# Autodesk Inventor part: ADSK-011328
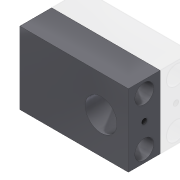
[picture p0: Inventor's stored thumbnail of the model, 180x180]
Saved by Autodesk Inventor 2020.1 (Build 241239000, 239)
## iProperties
Created: 1999-12
Part Number: ADSK-011328
Material: Acier doux
Description: PLT-04,FH,CP,10,022,032,955C,SUPPORT,SHAFT
Document SubType Name: Modeling
Designer: sspink
Density: 7.86 g/cm^3
Appearance: Metal-Steel(Polish)
Mass: 748.058 g
Surface Area: 230.906 cm^2
Volume: 95.1728 cm^3
Control State: 0
Checked Out: False
Last Check In By: sspink
Last Check In Date: 1999-12-22
Master: False
Shininess: 0.0
Length Units: 11269
Angle Units: 11279
Time Units: 11290
Mass Units: 11283
Length Display Precision: 3
Angle Display Precision: 2
Compacted: True
Dimensions: 85,5x57x25 mm
Mass: 0,748 kg
DocNumber: ADSK-011328.ipt
Folder: 01 - Themengebiete\Simplification\01 - Packaging machine\
VDS_Category: 3D Komponenten
Density: 0.0
Volumn: 0.0
Area: 0.0
PropertySet Name: Model Information
Author: sspink
Revision Number: -
Title: Support
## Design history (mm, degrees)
node "Solide1"
  node "Extrusion1" dims "d2" = 25, "d3" = 0
  node "Hole1" dims "d5" = 25, "d6" = 9.525, "d7" = 6.35, "d8" = 60 deg, "d9" = 19.05, "d10" = 118 deg, "d26" = 6
  node "Hole2" dims "d13" = 9, "d14" = 15, "d15" = 15, "d16" = 60 deg, "d17" = 19.05, "d18" = 118 deg, "d28" = 6
  node "Hole3" dims "d19" = 4.134, "d20" = 9.525, "d21" = 6.35, "d22" = 60 deg, "d23" = 14.2, "d24" = 118 deg, "d29" = 10
sketch "Sketch1"
  geometry: L1 (-42.75, 28.5)-(42.75, 28.5); L2 (42.75, 28.5)-(42.75, -28.5); L3 (42.75, -28.5)-(-42.75, -28.5); L4 (-42.75, -28.5)-(-42.75, 28.5); 3 further points
  constraints: 8 end point, 2 midpoint, 2 parallel, 1 horizontal, 1 horizontal alignment, 1 perpendicular, 1 vertical alignment
  dimensions: "d0" = 85.5 distance of L1.start L1.end; "d1" = 57 distance of L1.end L2.end
sketch "Sketch2"
  geometry: L1 (-42.75, -28.5)-(-42.75, 28.5) reference; L2 (42.75, 28.5)-(42.75, -28.5) reference; L3 (-42.75, 0)-(42.75, 0); 1 further point
  constraints: 2 end point, 2 midpoint, 1 point on line
  dimensions: "d4" = 21.5 distance from line of point (21.25, 0) L2
sketch "Sketch3"
  geometry: L1 (-12.5, 47.5)-(-12.5, 9.5); L2 (0, 57)-(-25, 57) reference; L3 (-25, 57)-(-25, 0) reference; 3 further points
  constraints: 3 midpoint, 2 end point, 1 horizontal alignment, 1 vertical, 1 vertical alignment
  dimensions: "d27" = 38 distance of L1.start L1.end
workplane "Work Plane1"
node "Corps solides"
node "Corps surfaciques"
sketch "Sketch4"
  geometry: L1 (-25, 57)-(-25, 0) reference; L2 (0, 0)-(-25, 0) reference; L3 (0, 0)-(0, 57) reference; L4 (0, 57)-(-25, 57) reference; L5 (-12.5, 57)-(-12.5, 0); L6 (-25, 28.5)-(0, 28.5); 1 further point
  constraints: 5 midpoint, 4 end point
other parameters: "d25" = -12.7
